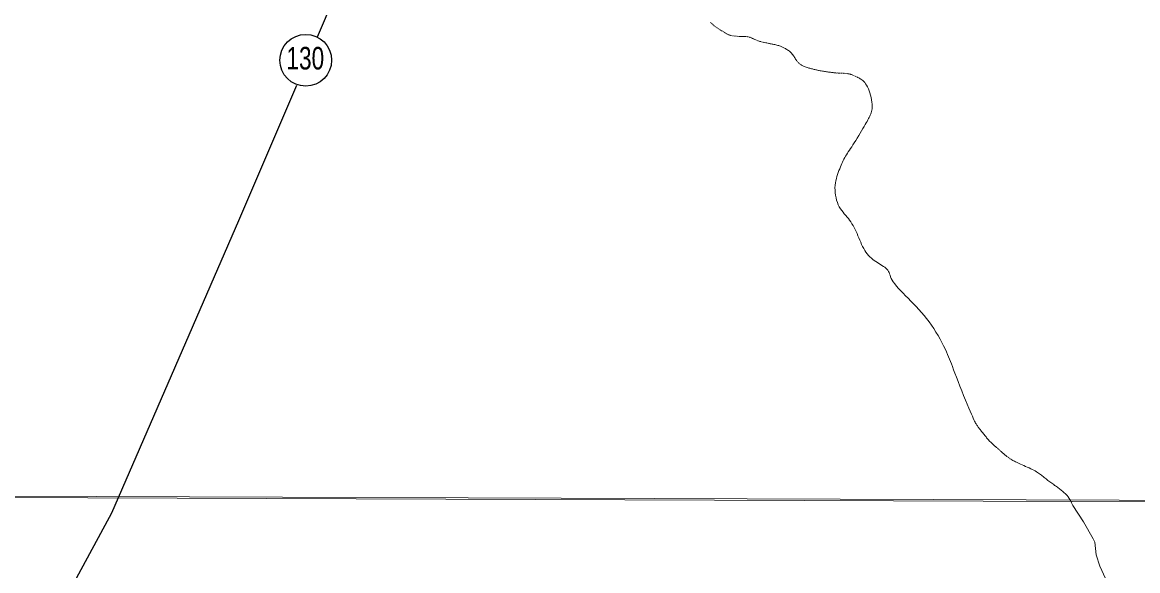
# Model space of a CAD drawing. Extents: x -1643653 to 4543381, y 1624270 to 13878484.
# Drawn here: x 600995 to 604455, y 8909688 to 8911389 of the extents above; entities that cross this region are included whole.
import ezdxf
from ezdxf.enums import TextEntityAlignment as Align

# ---------------------------------------------------------------- set-up
doc = ezdxf.new("R2010")
doc.units = 0
doc.header["$LTSCALE"] = 200
doc.layers.add('6', color=7, linetype='Continuous', lineweight=13)
doc.layers.add('60', color=7, linetype='Continuous', lineweight=13)

msp = doc.modelspace()

# ---------------------------------------------------------------- linework, layer by layer
at = {"layer": '6'}
for p, q in [((603131, 8911387.2), (603129.6, 8911388.4)), ((603133.4, 8911385.2), (603132.3, 8911386.2)), ((603135.6, 8911383.3), (603134.6, 8911384.2)), ((603137.8, 8911381.3), (603136.7, 8911382.3)), ((603140, 8911379.3), (603138.9, 8911380.3)), ((603142.6, 8911377.2), (603141.3, 8911378.3)), ((603145.4, 8911374.9), (603144, 8911376.1)), ((603148.5, 8911372.6), (603147, 8911373.8)), ((603151.7, 8911370.4), (603150.1, 8911371.5)), ((603154.8, 8911368.4), (603153.2, 8911369.4)), ((603157.8, 8911366.6), (603156.3, 8911367.5)), ((603160.7, 8911364.9), (603159.2, 8911365.7)), ((603163.5, 8911363.3), (603162.1, 8911364.1)), ((603166.3, 8911361.7), (603164.9, 8911362.5)), ((603169, 8911360.1), (603167.6, 8911360.9)), ((603171.7, 8911358.5), (603170.3, 8911359.3)), ((603174.4, 8911356.9), (603173, 8911357.7)), ((603177, 8911355.3), (603175.7, 8911356.1)), ((603179.7, 8911353.8), (603178.3, 8911354.6)), ((603182.2, 8911352.4), (603180.9, 8911353.1)), ((603184.6, 8911351.1), (603183.4, 8911351.7)), ((603186.8, 8911350.1), (603185.8, 8911350.6)), ((603188.9, 8911349.3), (603187.9, 8911349.7)), ((603191, 8911348.7), (603190, 8911349)), ((603193.3, 8911348.2), (603192.2, 8911348.4)), ((603196, 8911347.7), (603194.6, 8911347.9)), ((603199.1, 8911347.2), (603197.5, 8911347.5)), ((603202.3, 8911346.8), (603200.7, 8911347)), ((603205.5, 8911346.4), (603203.9, 8911346.6)), ((603208.6, 8911346), (603207.1, 8911346.2)), ((603211.6, 8911345.7), (603210.1, 8911345.9)), ((603214.3, 8911345.5), (603213, 8911345.6)), ((603217, 8911345.3), (603215.6, 8911345.4)), ((603219.5, 8911345.2), (603218.2, 8911345.2)), ((603222, 8911345.1), (603220.8, 8911345.1)), ((603224.5, 8911345), (603223.2, 8911345.1)), ((603226.9, 8911345), (603225.7, 8911345)), ((603229.2, 8911345), (603228, 8911345)), ((603231.5, 8911345), (603230.3, 8911345)), ((603233.7, 8911344.9), (603232.6, 8911344.9)), ((603235.8, 8911344.9), (603234.8, 8911344.9)), ((603237.8, 8911344.9), (603236.8, 8911344.9)), ((603240.7, 8911344.8), (603239.7, 8911344.9)), ((603243.6, 8911344.6), (603242.6, 8911344.7)), ((603245.8, 8911344.2), (603244.7, 8911344.4)), ((603248, 8911343.7), (603246.9, 8911344)), ((603250.4, 8911343), (603249.2, 8911343.4)), ((603252.9, 8911342.1), (603251.6, 8911342.6)), ((603255.5, 8911341.1), (603254.2, 8911341.6)), ((603258.1, 8911339.9), (603256.8, 8911340.5)), ((603263.3, 8911338.7), (603259.4, 8911339.3)), ((603263.5, 8911337.3), (603262.1, 8911338)), ((603266.4, 8911336), (603265, 8911336.7)), ((603269.4, 8911334.6), (603267.9, 8911335.3)), ((603272.5, 8911333.3), (603271, 8911334)), ((603275.8, 8911332.1), (603274.1, 8911332.7)), ((603279.1, 8911330.9), (603277.4, 8911331.5)), ((603282.5, 8911329.9), (603280.8, 8911330.4)), ((603285.8, 8911329), (603284.2, 8911329.4)), ((603289.1, 8911328.2), (603287.5, 8911328.6)), ((603292.1, 8911327.5), (603290.6, 8911327.8)), ((603294.9, 8911326.9), (603293.5, 8911327.2)), ((603297.7, 8911326.3), (603296.3, 8911326.6)), ((603300.8, 8911325.7), (603299.2, 8911326)), ((603304.2, 8911325), (603302.5, 8911325.3)), ((603308.2, 8911324.2), (603306.2, 8911324.6)), ((603400, 8911266.3), (603398.8, 8911267.7)), ((603402.3, 8911263.8), (603401.2, 8911265)), ((603404.7, 8911261.5), (603403.5, 8911262.6)), ((603407.4, 8911259.2), (603406, 8911260.3)), ((603523.2, 8911231.6), (603521.3, 8911231.8)), ((603526.6, 8911231.3), (603524.9, 8911231.5)), ((603529.7, 8911231.1), (603528.2, 8911231.2)), ((603532.4, 8911231), (603531.1, 8911231.1)), ((603534.9, 8911230.9), (603533.7, 8911231)), ((603537.3, 8911230.9), (603536.1, 8911230.9)), ((603539.6, 8911230.9), (603538.5, 8911230.9)), ((603542.1, 8911230.8), (603540.8, 8911230.9)), ((603544.8, 8911230.7), (603543.4, 8911230.8)), ((603547.8, 8911230.5), (603546.2, 8911230.7)), ((603551.4, 8911230.2), (603549.6, 8911230.4)), ((603574.8, 8911223.6), (603573, 8911224.4)), ((603578.2, 8911222), (603576.5, 8911222.8)), ((603581.7, 8911220.4), (603580, 8911221.2)), ((604054.2, 8910038.5), (604052.7, 8910039.6)), ((604056.9, 8910036.4), (604055.5, 8910037.4)), ((604059.7, 8910034.4), (604058.2, 8910035.4)), ((574653.9, 8910009.3), (626625.7, 8909822.1))]:
    msp.add_line(p, q, dxfattribs=at)
msp.add_lwpolyline([(607600.8, 8920952.4), (596639.8, 8920989.8), (596608.8, 8909934.4), (607569.8, 8909894.9)], close=True, dxfattribs=at)
at = {"layer": '6', "lineweight": 25}
for points in [[(601910.1, 8911344.1), (602223.7, 8912077.8), (602313.4, 8912293.8), (602321.9, 8912321.1), (602252.1, 8912505.5), (602217.1, 8912579.8), (602219.3, 8912630.5)], [(601054.1, 8909463.7), (601272.1, 8909867.7), (601666.5, 8910774.3), (601846, 8911194.3)]]:
    msp.add_lwpolyline(points, dxfattribs=at)
at = {"layer": '6'}
for points in [[(603397.7, 8911269.3), (603396.5, 8911271), (603395.2, 8911273), (603393.8, 8911275.2), (603392.4, 8911277.6), (603390.8, 8911280.1), (603389.2, 8911282.7), (603387.4, 8911285.3), (603385.5, 8911287.9), (603383.5, 8911290.4), (603381.4, 8911292.9), (603379.1, 8911295.2), (603376.7, 8911297.3), (603374.3, 8911299.2), (603371.8, 8911301.1), (603369.3, 8911302.8), (603366.8, 8911304.4), (603364.4, 8911305.9), (603362, 8911307.3), (603359.8, 8911308.6), (603357.7, 8911309.8), (603355.6, 8911311), (603353.5, 8911312.1), (603351.4, 8911313.1), (603349.1, 8911314.1), (603346.8, 8911315), (603344.3, 8911315.9), (603341.6, 8911316.8), (603338.7, 8911317.6), (603335.7, 8911318.3), (603332.7, 8911319), (603329.6, 8911319.7), (603326.5, 8911320.4), (603323.5, 8911321), (603320.6, 8911321.6), (603317.8, 8911322.2), (603315.2, 8911322.7), (603312.7, 8911323.2), (603310.4, 8911323.7), (603308.2, 8911324.2)], [(603412.3, 8911255.9), (603410.6, 8911257), (603408.9, 8911258.1)], [(603519.3, 8911232), (603517.2, 8911232.3), (603515, 8911232.5), (603512.6, 8911232.8), (603510.1, 8911233.1), (603507.5, 8911233.4), (603504.8, 8911233.7), (603501.9, 8911234.1), (603498.9, 8911234.4), (603495.9, 8911234.8), (603492.8, 8911235.2), (603489.6, 8911235.7), (603486.4, 8911236.1), (603483.2, 8911236.6), (603479.9, 8911237.1), (603476.7, 8911237.7), (603473.5, 8911238.2), (603470.3, 8911238.8), (603467.3, 8911239.3), (603464.3, 8911239.9), (603461.5, 8911240.5), (603458.7, 8911241.1), (603456.1, 8911241.7), (603453.6, 8911242.3), (603451.1, 8911242.9), (603448.6, 8911243.5), (603446.1, 8911244.2), (603443.5, 8911244.8), (603440.8, 8911245.6), (603438.1, 8911246.3), (603435.2, 8911247.2), (603432.3, 8911248), (603429.4, 8911248.9), (603426.5, 8911249.8), (603423.8, 8911250.8), (603421.1, 8911251.7), (603418.6, 8911252.8), (603416.3, 8911253.8), (603414.2, 8911254.8), (603412.3, 8911255.9)], [(603571.2, 8911225.2), (603569.3, 8911226), (603567.5, 8911226.7), (603565.6, 8911227.4), (603563.6, 8911228), (603561.6, 8911228.6), (603559.5, 8911229), (603557.4, 8911229.4), (603555.4, 8911229.7), (603553.4, 8911230)], [(603618, 8911086.3), (603620.1, 8911090.4), (603622, 8911094.2), (603623.8, 8911097.9), (603625.3, 8911101.4), (603626.8, 8911104.9), (603628.2, 8911108.4), (603629.3, 8911112.1), (603630.3, 8911116), (603631, 8911120.2), (603631.4, 8911124.8), (603631.4, 8911129.9), (603631.1, 8911135.5), (603630.4, 8911141.8), (603629.3, 8911148.5), (603627.9, 8911155.6), (603626.2, 8911162.7), (603624.1, 8911169.8), (603621.9, 8911176.7), (603619.4, 8911183.1), (603616.7, 8911188.9), (603613.9, 8911194.1), (603611, 8911198.5), (603608.1, 8911202.2), (603605.1, 8911205.4), (603602.1, 8911208.1), (603599.3, 8911210.4), (603596.5, 8911212.3), (603593.9, 8911213.9), (603591.5, 8911215.4), (603589.3, 8911216.6), (603587.2, 8911217.7), (603585.3, 8911218.7), (603583.5, 8911219.6)], [(603517.6, 8910852.6), (603516.6, 8910860.4), (603516, 8910868.2), (603515.9, 8910875.9), (603516.4, 8910883.3), (603517.3, 8910890.6), (603518.6, 8910897.6), (603520.2, 8910904.3), (603522, 8910910.9), (603524, 8910917.2), (603526.1, 8910923.3), (603528.3, 8910929.2), (603530.5, 8910934.9), (603532.6, 8910940.3), (603534.8, 8910945.6), (603536.9, 8910950.7), (603539.1, 8910955.6), (603541.4, 8910960.3), (603543.8, 8910964.9), (603546.2, 8910969.4), (603548.7, 8910973.8), (603551.4, 8910978.2), (603554.3, 8910982.6), (603557.3, 8910987.2), (603560.5, 8910992.1), (603564, 8910997.2), (603567.7, 8911002.8), (603571.6, 8911008.9), (603575.9, 8911015.5), (603580.4, 8911022.6), (603585, 8911030), (603589.6, 8911037.5), (603594.1, 8911045), (603598.5, 8911052.3), (603602.6, 8911059.3), (603606.5, 8911065.8), (603609.9, 8911071.7), (603612.9, 8911077), (603615.6, 8911081.8), (603618, 8911086.3)], [(603657.1, 8910637.5), (603652.4, 8910640.4), (603647.5, 8910643.4), (603642.7, 8910646.6), (603638, 8910650), (603633.3, 8910653.6), (603628.7, 8910657.4), (603624.2, 8910661.6), (603620, 8910666), (603615.9, 8910670.8), (603612, 8910676), (603608.4, 8910681.6), (603605, 8910687.5), (603601.8, 8910693.7), (603598.7, 8910700.1), (603595.7, 8910706.7), (603592.9, 8910713.4), (603590, 8910720.2), (603587.2, 8910726.8), (603584.3, 8910733.4), (603581.4, 8910739.9), (603578.4, 8910746.3), (603575.3, 8910752.4), (603572.1, 8910758.4), (603568.7, 8910764.2), (603565.2, 8910769.8), (603561.4, 8910775.1), (603557.5, 8910780.1), (603553.3, 8910785), (603549.1, 8910789.8), (603544.9, 8910794.7), (603540.8, 8910799.7), (603536.8, 8910804.9), (603533, 8910810.5), (603529.4, 8910816.5), (603526.3, 8910823), (603523.5, 8910830), (603521.1, 8910837.3), (603519.2, 8910844.9), (603517.6, 8910852.6)], [(603865.2, 8910358.8), (603861.6, 8910366.9), (603857.5, 8910375.8), (603852.8, 8910385.4), (603847.6, 8910395.6), (603841.9, 8910406.2), (603835.8, 8910417.1), (603829.3, 8910428), (603822.5, 8910438.9), (603815.3, 8910449.7), (603807.8, 8910460), (603800.1, 8910470), (603792.2, 8910479.8), (603784.1, 8910489.2), (603775.9, 8910498.3), (603767.6, 8910507.2), (603759.3, 8910515.9), (603751.1, 8910524.4), (603742.8, 8910532.7), (603734.8, 8910540.8), (603727.1, 8910548.7), (603719.7, 8910556.3), (603712.9, 8910563.6), (603706.8, 8910570.6), (603701.4, 8910577.2), (603696.9, 8910583.4), (603693.4, 8910589.2), (603690.7, 8910594.5), (603688.5, 8910599.5), (603686.8, 8910604.1), (603685.3, 8910608.4), (603683.8, 8910612.4), (603682, 8910616.1), (603679.9, 8910619.6), (603677.2, 8910622.8), (603673.9, 8910625.9), (603670.2, 8910628.9), (603666.1, 8910631.8), (603661.7, 8910634.6), (603657.1, 8910637.5)], [(603978.6, 8910109.9), (603976.6, 8910112.4), (603974.6, 8910114.9), (603972.6, 8910117.3), (603970.6, 8910119.8), (603968.7, 8910122.2), (603966.9, 8910124.5), (603965.1, 8910126.8), (603963.5, 8910128.9), (603961.9, 8910130.9), (603960.5, 8910132.9), (603959.1, 8910134.8), (603957.8, 8910136.7), (603956.5, 8910138.8), (603955.1, 8910140.9), (603953.8, 8910143.2), (603952.3, 8910145.8), (603950.8, 8910148.6), (603949.1, 8910152), (603947.1, 8910155.9), (603944.8, 8910160.8), (603942.2, 8910166.6), (603939.1, 8910173.7), (603935.4, 8910182.2), (603931.2, 8910192.3), (603926.3, 8910204.1), (603920.9, 8910217.2), (603915.1, 8910231.3), (603909.2, 8910245.8), (603903.4, 8910260.5), (603897.7, 8910274.8), (603892.4, 8910288.2), (603887.7, 8910300.5), (603883.6, 8910311.2), (603880.1, 8910320.7), (603877, 8910329.1), (603874.1, 8910336.7), (603871.2, 8910344.1), (603868.3, 8910351.3), (603865.2, 8910358.8)], [(604051.2, 8910040.8), (604049.5, 8910042.2), (604047.8, 8910043.5), (604046, 8910045), (604044.1, 8910046.5), (604042.3, 8910048), (604040.4, 8910049.6), (604038.6, 8910051.2), (604036.8, 8910052.7), (604035, 8910054.3), (604033.3, 8910055.9), (604031.6, 8910057.4), (604029.9, 8910058.9), (604028.3, 8910060.4), (604026.7, 8910061.8), (604025.1, 8910063.2), (604023.6, 8910064.5), (604022.1, 8910065.8), (604020.5, 8910067.1), (604019, 8910068.4), (604017.3, 8910069.7), (604015.7, 8910071.1), (604013.9, 8910072.7), (604012, 8910074.3), (604010, 8910076), (604007.9, 8910077.9), (604005.8, 8910079.9), (604003.5, 8910082), (604001.3, 8910084.1), (603999, 8910086.3), (603996.8, 8910088.6), (603994.6, 8910090.9), (603992.5, 8910093.2), (603990.4, 8910095.5), (603988.4, 8910097.9), (603986.4, 8910100.2), (603984.5, 8910102.6), (603982.5, 8910105), (603980.6, 8910107.4), (603978.6, 8910109.9)], [(604137, 8909997.1), (604132.8, 8909999.4), (604128.1, 8910001.8), (604123.1, 8910004.2), (604117.9, 8910006.6), (604112.6, 8910009), (604107.2, 8910011.4), (604101.8, 8910013.8), (604096.7, 8910016), (604091.8, 8910018.2), (604087.2, 8910020.2), (604083.1, 8910022.1), (604079.2, 8910023.9), (604075.8, 8910025.6), (604072.6, 8910027.2), (604069.8, 8910028.6), (604067.2, 8910029.9), (604065, 8910031.2), (604063, 8910032.3), (604061.3, 8910033.4)], [(604253.8, 8909889.8), (604249.8, 8909898.4), (604246.1, 8909905.6), (604242.5, 8909911.6), (604239.1, 8909916.6), (604235.9, 8909920.7), (604232.8, 8909924.1), (604229.9, 8909927), (604227, 8909929.5), (604224.3, 8909931.9), (604221.6, 8909934.2), (604219, 8909936.4), (604216.4, 8909938.5), (604213.8, 8909940.6), (604211.2, 8909942.6), (604208.5, 8909944.5), (604205.9, 8909946.5), (604203.1, 8909948.5), (604200.3, 8909950.5), (604197.4, 8909952.5), (604194.5, 8909954.6), (604191.6, 8909956.7), (604188.6, 8909958.8), (604185.7, 8909961), (604182.7, 8909963.2), (604179.7, 8909965.5), (604176.7, 8909967.8), (604173.7, 8909970.1), (604170.8, 8909972.5), (604167.8, 8909974.9), (604164.9, 8909977.2), (604162.1, 8909979.5), (604159.2, 8909981.8), (604156.4, 8909984), (604153.6, 8909986.2), (604150.7, 8909988.4), (604147.6, 8909990.5), (604144.3, 8909992.7), (604140.8, 8909994.9), (604137, 8909997.1)], [(604366.2, 8909638.2), (604338, 8909702), (604326.5, 8909737.2), (604322.2, 8909776.3), (604317.2, 8909786.9), (604287.3, 8909838.8), (604253.8, 8909889.8)]]:
    msp.add_lwpolyline(points, dxfattribs=at)
at = {"layer": '6', "lineweight": 25}
msp.add_circle((601874.1, 8911271.4), 80.3, dxfattribs=at)
at = {"layer": '60', "lineweight": 25}
msp.add_spline([(814781, 9009175.5), (814787.2, 9009173.4), (814796.9, 9009173.4), (814799.4, 9009172.4), (814805.1, 9009174.5), (814805.6, 9009176.5), (814811.7, 9009179.5), (814811.7, 9009179.5), (814801.5, 9009181), (814790.7, 9009181.5), (814784.1, 9009183.1), (814777.4, 9009185.1), (814778.4, 9009175.5)], degree=3, dxfattribs=at)

# ---------------------------------------------------------------- texts
at = {"layer": '6', "width": 0.75}
msp.add_text('130', height=70, dxfattribs=at).set_placement((601872.6, 8911242.7), align=Align.CENTER)

doc.saveas('drawing.dxf')
